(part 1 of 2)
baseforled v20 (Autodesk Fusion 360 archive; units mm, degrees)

design "baseforled" references "Petal", "linkagestopper", "FinalprojectPCBnew", "cup", "Seervo-horn", "sensormountnyt1", "Linkage", "Tower Pro MG90S Micro servo"
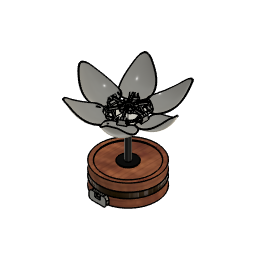
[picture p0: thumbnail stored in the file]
description: STEP AP214
part number: Tower Pro MG90S Micro servo
description: Part Number
part number: Untitled
parameter "d13_1" = 0
parameter "d14_1" = 10
sketch "Sketch1" plane through (0, 0, 0) normal (0, 0, 1) x axis (1, 0, 0)
  circle C1 centre (0, 0) radius 50
  point P1 (0, 0)
  point P2 (0, 0)
  coincident P1 P2
  dimension "d1" diameter C1 = 100
extrude "Extrude1" new body sketch "Sketch1" along normal blind 40
sketch "Sketch2" plane through (0, 0, 40) normal (0, 0, 1) x axis (-1, 0, 0)
  line L1 (15, 0) -> (0, 0)
  circle C1 centre (0, 0) radius 50
  circle C2 centre (0, 0) radius 15
  circle C3 centre (0, 0) radius 5
  circle C4 centre (0, 0) radius 1.5
  circle C5 centre (11, 0) radius 2.5
  circle C6 centre (-5.5, 9.5263) radius 2.5
  circle C7 centre (-5.5, -9.5263) radius 2.5
  point P3 (0, 0)
  point P6 (0, 0)
  point P7 (15, 0)
  point P8 (11, 0)
  point P4 (0, 0)
  concentric C1 C2
  concentric C2 C3
  concentric C3 C4
  coincident P3 P6
  coincident C2 P7
  horizontal L1
  coincident L1 P8
  dimension "d4" diameter C2 = 30
  dimension "d5" diameter C3 = 10
  dimension "d6" diameter C4 = 3
  dimension "d10" diameter C5 = 5
  dimension "d11" distance P4 P8 = 11
  dimension "d13" C-Pattern1-Angle = 360
shell "Shell1" innerThickness 6
extrude "Extrude2" cut sketch "Sketch2" profile of C3 C4 against normal blind 6
extrude "Extrude1" new body sketch "Sketch2" profile of C2 C3 C4 C5 C6 C7 against normal blind 3
extrude "Extrude2" add sketch "Sketch2" profile of C5 C6 C7 against normal blind 6
extrude "Extrude3" add sketch "Sketch2" profile of C3 C4 against normal blind 8 and along normal blind 50
extrude "Extrude3" add of existing geometry blind 2
combine "Combine1"
sketch "Sketch3" plane through (0, 0, 34) normal (0, 0, 1) x axis (-1, 0, 0)
  circle C1 centre (-5.5, 9.5263) radius 2.5
  circle C2 centre (11, 0) radius 2.5
  circle C3 centre (-5.5, -9.5263) radius 2.5
  circle C4 centre (11, 0) radius 1.5
  circle C5 centre (-5.5, -9.5263) radius 1.5
  circle C6 centre (-5.5, 9.5263) radius 1.5
  concentric C2 C4
  concentric C3 C5
  concentric C1 C6
  dimension "d24" diameter C4 = 3
  dimension "d25" diameter C5 = 3
  dimension "d26" diameter C6 = 3
extrude "Extrude4" cut sketch "Sketch3" profile of C4 C5 C6 against normal blind 2
sketch "Sketch4" plane through (0, 0, 0) normal (0, 0, -1) x axis (1, 0, 0)
  line L1 (-47, 0) -> (0, 0)
  circle C1 centre (0, 0) radius 44
  circle C2 centre (0, 0) radius 50
  circle C3 centre (0, 0) radius 47
  circle C4 centre (-37, 0) radius 1.5
  circle C5 centre (0, -37) radius 1.5
  circle C6 centre (37, 0) radius 1.5
  circle C7 centre (0, 37) radius 1.5
  point P3 (0, 0)
  point P4 (0, 0)
  point P6 (-37, 0)
  point P5 (-47, 0)
  concentric C1 C3
  coincident P3 P4
  horizontal L1
  coincident L1 P6
  coincident C3 P5
  dimension "d31" diameter C3 = 94
  dimension "d32" diameter C4 = 3
  dimension "d33" distance P5 P6 = 10
  dimension "d35" C-Pattern1-Angle = 360
extrude "Extrude5" cut sketch "Sketch4" profile of C1 C3 against normal blind 2.8
extrude "Extrude1" new body sketch "Sketch4" profile of C1 C3 C4 C5 C6 C7 against normal blind 2.8
external_derived "ExternalDerived1"
derived_instance "DerivedInstance1"
component_insert "Component Insert3"
component_insert "Component Insert4"
position "Position1"
sketch "Sketch5" plane through (0, 0, 90) normal (0, 0, 1) x axis (-1, 0, 0)
  circle C1 centre (0, 0) radius 1.5
  circle C2 centre (0, 0) radius 5
  circle C3 centre (0, 0) radius 1
  concentric C1 C3
extrude "Extrude1" new body sketch "Sketch5" profile of C3 against normal blind 100
sketch "Sketch6" plane through (0, 0, 0) normal (0, 1, 0) x axis (1, 0, 0)
  circle C1 centre (0, 13) radius 1.25
  circle C2 centre (0, 13) radius 2
  concentric C1 C2
  dimension "d42" diameter C1 = 2.5
sketch "Sketch8" plane through (0, 0, 0) normal (0, 0, 1) x axis (1, 0, 0)
  circle C1 centre (0, -4) radius 1
sketch "Sketch9" plane through (0, 0, 0) normal (1, 0, 0) x axis (0, 1, 0)
  arc A1 centre (-3.1069, -12.5) radius 1.0235 clockwise from (-4, -13) to (-3.0095, -11.4811)
position "Position2"
position "Position3"
extrude "Extrude8" cut of existing geometry blind -6
move "Move3"
position "Position13"
sketch "Sketch14" plane through (0, -3.0543, 0) normal (0, 1, 0) x axis (-1, 0, 0)
  line L1 (3.8332, 6.2534) -> (-10.7858, 4.8708)
  line L2 (-10.763, 11.5994) -> (3.8332, 10.2534)
  line L3 (-1.5977, 13.5422) -> (-4.0509, 13.5422)
  line L4 (-1.5977, 5.7397) -> (-1.5977, 13.5422)
  line L5 (-4.0509, 5.7397) -> (-1.5977, 5.7397)
  line L6 (-4.0509, 13.5422) -> (-4.0509, 5.7397)
  circle C1 centre (-0.3736, 8.2236) radius 0.5
  circle C2 centre (-2.9004, 8.2207) radius 0.5
  circle C3 centre (4.4334, 8.2381) radius 0.5
  circle C4 centre (-5.3079, 8.2364) radius 0.5
  circle C5 centre (2.0164, 8.2396) radius 0.5
  arc A1 centre (-12.177, 8.2398) radius 3.645 clockwise from (-10.763, 11.5994) to (-10.7858, 4.8708)
  arc A2 centre (3.6441, 8.2534) radius 2.0089 clockwise from (3.8332, 10.2534) to (3.8332, 6.2534)
  point P15 (-1.5977, 5.7397)
  horizontal L3
  vertical L4
  horizontal L5
  vertical L6
  coincident L1 P15
extrude "Extrude12" new body sketch "Sketch14" profile of C2 L2 L3 L4 L5 L6 along normal blind 2
extrude "Extrude13" add of existing geometry blind 3
extrude "Extrude14" add of existing geometry blind 1
extrude "Extrude15" add of existing geometry blind 1
position "Position14"
sketch "Sketch15" plane through (0, -1.0543, 0) normal (0, 1, 0) x axis (-1, 0, 0)
  line L1 (-0.5977, 5.7397) -> (-5.0509, 5.7397)
  line L2 (-0.5977, 16.5422) -> (-0.5977, 5.7397)
  line L3 (-5.0509, 16.5422) -> (-0.5977, 16.5422)
  line L4 (-5.0509, 5.7397) -> (-5.0509, 16.5422)
  circle C1 centre (-2.9004, 8.2207) radius 0.5
  circle C2 centre (-3, 13) radius 1
extrude "Extrude16" cut sketch "Sketch15" profile of C2 against normal blind 4
move "Move4"
position "Position15"
sketch "Sketch16" plane through (0, -1.0543, 0) normal (0, 1, 0) x axis (-1, 0, 0)
  line L1 (-0.5977, 5.7397) -> (-5.0509, 5.7397)
  line L2 (-0.5977, 16.5422) -> (-0.5977, 5.7397)
  line L3 (-5.0509, 16.5422) -> (-0.5977, 16.5422)
  line L4 (-5.0509, 5.7397) -> (-5.0509, 16.5422)
  circle C1 centre (-3, 13) radius 1
  circle C2 centre (-2.9004, 8.2207) radius 0.5
  circle C3 centre (-2.9004, 8.2207) radius 0.6945
  concentric C2 C3
extrude "Extrude17" new body sketch "Sketch16" profile of C2 C3 along normal blind 0.4
sketch "Sketch17" plane through (0, -0.6543, 0) normal (0, 1, 0) x axis (-1, 0, 0)
  line L1 (-2.8, 8.7) -> (-3, 8.7)
  line L2 (-2.8, 7.8) -> (-2.8, 8.7)
  line L3 (-3, 7.8) -> (-2.8, 7.8)
  line L4 (-3, 8.7) -> (-3, 7.8)
  line L5 (-2.5, 8.4) -> (-3.3, 8.4)
  line L6 (-2.5, 8.2) -> (-2.5, 8.4)
  line L7 (-3.3, 8.2) -> (-2.5, 8.2)
  line L8 (-3.3, 8.4) -> (-3.3, 8.2)
  circle C1 centre (-2.9004, 8.2207) radius 0.6945
  horizontal L1
  vertical L2
  horizontal L3
  vertical L4
  horizontal L5
  vertical L6
  horizontal L7
  vertical L8
extrude "Extrude18" cut sketch "Sketch17" profile of L1 L2 L3 L4 L5 L6 L7 L8 against normal blind 0.1
fillet "Fillet2" radius 0.15
fillet "Fillet3" radius 0.05
sketch "Sketch18" plane through (0, -1.0543, 0) normal (0, -1, 0) x axis (1, 0, 0)
  circle C1 centre (2.9004, 8.2207) radius 0.6945
  circle C2 centre (2.9004, 8.2207) radius 0.3922
  concentric C1 C2
extrude "Extrude19" add sketch "Sketch18" profile of C2 along normal blind 5
thread "Thread1" ThreadOffset 0 ThreadLength 4.7
sketch "Sketch19" plane through (0, -6.0543, 0) normal (0, -1, 0) x axis (1, 0, 0)
  line L1 (3.2968, 8.2207) -> (3.0986, 7.8774)
  line L2 (3.0986, 8.5639) -> (3.2968, 8.2207)
  line L3 (2.7022, 8.5639) -> (3.0986, 8.5639)
  line L4 (2.5041, 8.2207) -> (2.7022, 8.5639)
  line L5 (2.7022, 7.8774) -> (2.5041, 8.2207)
  line L6 (3.0986, 7.8774) -> (2.7022, 7.8774)
  line L7 (3.4502, 8.2207) -> (3.1753, 7.7446)
  line L8 (3.1753, 8.6968) -> (3.4502, 8.2207)
  line L9 (2.6255, 8.6968) -> (3.1753, 8.6968)
  line L10 (2.3506, 8.2207) -> (2.6255, 8.6968)
  line L11 (2.6255, 7.7446) -> (2.3506, 8.2207)
  line L12 (3.1753, 7.7446) -> (2.6255, 7.7446)
  circle C1 centre (2.9004, 8.2207) radius 0.3432
  point P2 (2.9004, 8.2207)
  point P9 (2.9004, 8.2207)
  point P16 (2.9004, 8.2207)
  coincident P2 P9
  coincident P9 P16
extrude "Extrude20" new body sketch "Sketch19" profile of L1 L2 L3 L4 L5 L6 L7 L8 L9 L10 L11 L12 against normal blind 0.3
move "Move5"
fillet "Fillet4" radius 0.25
sketch "Sketch20" plane through (0, 0, 2.1397) normal (0, 0, -1) x axis (1, 0, 0)
  line L1 (-4.0751, 30.4976) -> (17.8749, 30.4976)
  line L2 (-4.0751, 20.1476) -> (-4.0751, 30.4976)
  line L3 (17.8749, 20.1476) -> (-4.0751, 20.1476)
  line L4 (17.8749, 30.4976) -> (17.8749, 20.1476)
  line L5 (-9.5017, 18) -> (23, 18)
  line L6 (-9.5017, 25.3226) -> (-9.5017, 18)
  line L7 (23, 25.3226) -> (-9.5017, 25.3226)
  line L8 (23, 18) -> (23, 25.3226)
  line L9 (18.8749, 18) -> (23, 18)
  line L10 (18.8749, 25.3226) -> (18.8749, 18)
  line L11 (23, 25.3226) -> (18.8749, 25.3226)
  line L12 (23, 18) -> (23, 25.3226)
  line L13 (-9.5017, 18) -> (-5, 18)
  line L14 (-9.5017, 25.3226) -> (-9.5017, 18)
  line L15 (-5, 25.3226) -> (-9.5017, 25.3226)
  line L16 (-5, 18) -> (-5, 25.3226)
  point P11 (18.8749, 25.3226)
  point P13 (-5, 18)
  horizontal L5
  vertical L6
  horizontal L7
  vertical L8
  horizontal L9
  vertical L10
  horizontal L11
  vertical L12
  coincident L7 P11
  horizontal L13
  vertical L14
  horizontal L15
  vertical L16
  coincident L5 P13
position "Position16"
sketch "Sketch23" plane through (0, -14.8476, 0) normal (0, 1, 0) x axis (-1, 0, 0)
  line L1 (3.7945, 5.0396) -> (3.7945, 16.4396)
  line L2 (8.1195, 5.0396) -> (3.7945, 5.0396)
  line L3 (8.3695, 10.0396) -> (8.3695, 5.2896)
  line L4 (7.5962, 10.0396) -> (8.3695, 10.0396)
  line L5 (8.3695, 11.4396) -> (7.5962, 11.4396)
  line L6 (8.3695, 16.1896) -> (8.3695, 11.4396)
  line L7 (3.7945, 16.4396) -> (8.1195, 16.4396)
  arc A1 centre (8.1195, 5.2896) radius 0.25 clockwise from (8.3695, 5.2896) to (8.1195, 5.0396)
  arc A2 centre (6.2695, 10.7396) radius 1.5 clockwise from (7.5962, 10.0396) to (7.5962, 11.4396)
  arc A3 centre (8.1195, 16.1896) radius 0.25 clockwise from (8.1195, 16.4396) to (8.3695, 16.1896)
  circle C1 centre (6.2695, 10.7396) radius 2
  circle C2 centre (-21.162, 10.6554) radius 2
  concentric A2 C1
  dimension "d172" diameter C1 = 4
  dimension "d173" diameter C2 = 4
move "Move1"
position "Position17"
extrude "Extrude6" cut blind -1
move "Move10"
move "Move12"
move "Move13"
move "Move14"
move "Move15"
move "Move16"
move "Move18"
move_face "MoveFace1"
extrude "Extrude7" add of existing geometry blind 10
sketch "Sketch34" plane through (0, 0, 21.7985) normal (0, 0, -1) x axis (1, 0, 0)
  circle C1 centre (8.9248, 8.0461) radius 1.5
  circle C2 centre (-7.5752, -1.4802) radius 1.5
  circle C3 centre (8.9248, -11.0065) radius 1.5
  circle C4 centre (3.4248, -1.4802) radius 5
  circle C5 centre (3.4248, -1.4802) radius 44
  circle C6 centre (3.4248, -1.4802) radius 14.9303
  concentric C4 C6
  dimension "d484" diameter C1 = 3
extrude "Extrude8" add sketch "Sketch34" profile of C1 C2 C3 C4 C6 against normal blind 15
position "Position18"
extrude "Extrude9" cut of existing geometry blind -5
position "Position19"
extrude "Extrude10" cut of existing geometry blind -5
position "Position20"
sketch "Sketch35" plane through (0, 0, 31.7985) normal (0, 0, -1) x axis (1, 0, 0)
  line L1 (47.1324, -6.5447) -> (-40.2828, -6.5447)
  circle C1 centre (3.4248, -1.4802) radius 44
  circle C2 centre (8.9248, 8.0461) radius 1.5
  circle C3 centre (-7.5752, -1.4802) radius 1.5
  circle C4 centre (8.9248, -11.0065) radius 1.5
  circle C5 centre (3.4248, -1.4802) radius 5
  point P3 (-40.2828, -6.5447)
  point P4 (47.1324, -6.5447)
  coincident C1 P3
  coincident C1 P4
  horizontal L1
extrude "Extrude11" add sketch "Sketch35" profile of C1 L1 along normal blind 20
extrude "Extrude12" cut sketch "Sketch34" profile of C1 C2 C3 C4 C6 against normal blind 15
extrude "Extrude13" new body sketch "Sketch34" profile of C1 C2 C3 C4 C6 against normal blind 15 and against normal blind 10
delete_face "DeleteFace1"
extrude "Extrude14" cut of existing geometry blind 22
extrude "Extrude15" cut of existing geometry blind -20
extrude "Extrude17" add of existing geometry blind 5
sketch "Sketch39" plane through (0, 0, 14.7896) normal (0, 0, -1) x axis (1, 0, 0)
  line L1 (-3.4945, 30.4976) -> (18.4555, 30.4976)
  line L2 (-3.4945, 20.1476) -> (-3.4945, 30.4976)
  line L3 (18.4555, 20.1476) -> (-3.4945, 20.1476)
  line L4 (18.4555, 30.4976) -> (18.4555, 20.1476)
extrude "Extrude38" new body sketch "Sketch20" profile of L2 L3 L4 L5 L6 L7 L8 L9 L10 L11 L12 L13 L14 L15 L16 against normal blind 7 and against normal blind 10
sketch "Sketch40" plane through (0, 0, 9.1397) normal (0, 0, -1) x axis (1, 0, 0)
  line L1 (-9.5017, 18) -> (-9.5017, 25.3226)
  line L2 (23, 18) -> (-9.5017, 18)
  line L3 (23, 25.3226) -> (23, 18)
  line L4 (-9.5017, 25.3226) -> (23, 25.3226)
  line L5 (19.5, 18) -> (23, 18)
  line L6 (19.5, 25.3226) -> (19.5, 18)
  line L7 (23, 25.3226) -> (19.5, 25.3226)
  line L8 (23, 18) -> (23, 25.3226)
  line L9 (-6.0017, 18) -> (-9.5017, 18)
  line L10 (-6.0017, 25.3226) -> (-6.0017, 18)
  line L11 (-9.5017, 25.3226) -> (-6.0017, 25.3226)
  line L12 (-9.5017, 18) -> (-9.5017, 25.3226)
  point P4 (23, 18)
  point P6 (23, 18)
  point P3 (-9.5017, 18)
  point P10 (-9.5017, 18)
  point P7 (19.5, 18)
  point P11 (-6.0017, 18)
  horizontal L5
  vertical L6
  horizontal L7
  vertical L8
  coincident P4 P6
  horizontal L9
  vertical L10
  horizontal L11
  vertical L12
  coincident P3 P10
  dimension "d267" distance P6 P7 = 3.5
  dimension "d268" distance P10 P11 = 3.5
extrude "Extrude39" add sketch "Sketch40" profile of L2 L3 L4 L5 L6 L7 L8 against normal blind 19
extrude "Extrude40" add sketch "Sketch40" profile of L1 L2 L4 L9 L10 L11 L12 against normal blind 19
extrude "Extrude41" add of existing geometry blind 2
extrude "Extrude42" add of existing geometry blind 1
extrude "Extrude44" add of existing geometry blind 1
position "Position22"
sketch "Sketch41" plane through (0, -18, 0) normal (0, 1, 0) x axis (-1, 0, 0)
  line L1 (-18.5, 13.1397) -> (4.0017, 13.1397)
  line L2 (-18.5, 28.1397) -> (-18.5, 13.1397)
  line L3 (-23, 28.1397) -> (-18.5, 28.1397)
  line L4 (-23, 9.1397) -> (-23, 28.1397)
  line L5 (9.5017, 9.1397) -> (-23, 9.1397)
  line L6 (9.5017, 28.1397) -> (9.5017, 9.1397)
  line L7 (4.0017, 28.1397) -> (9.5017, 28.1397)
  line L8 (-6.7491, 31.2966) -> (-6.7491, 5)
  line L9 (4.0017, 13.1397) -> (4.0017, 28.1397)
  circle C1 centre (7.171, 20.7271) radius 1.5
  circle C2 centre (-20.6693, 20.7271) radius 1.5
  perpendicular L5 L8
  symmetric L8 C1 C2
  dimension "d283" diameter C1 = 3
  dimension "d284" diameter C2 = 3
extrude "Extrude45" cut sketch "Sketch41" profile of C1 C2 against normal blind 10
sketch "Sketch42" plane through (0, -14.807, 0) normal (0, 1, 0) x axis (-1, 0, 0)
  line L1 (4.24, 15.1104) -> (4.24, 26.5104)
  line L2 (8.565, 15.1104) -> (4.24, 15.1104)
  line L3 (8.815, 20.1104) -> (8.815, 15.3604)
  line L4 (8.0417, 20.1104) -> (8.815, 20.1104)
  line L5 (8.815, 21.5104) -> (8.0417, 21.5104)
  line L6 (8.815, 26.2604) -> (8.815, 21.5104)
  line L7 (4.24, 26.5104) -> (8.565, 26.5104)
  arc A1 centre (8.565, 15.3604) radius 0.25 clockwise from (8.815, 15.3604) to (8.565, 15.1104)
  arc A2 centre (6.715, 20.8104) radius 1.5 clockwise from (8.0417, 20.1104) to (8.0417, 21.5104)
  arc A3 centre (8.565, 26.2604) radius 0.25 clockwise from (8.565, 26.5104) to (8.815, 26.2604)
  circle C1 centre (6.715, 20.8104) radius 2
  circle C2 centre (-20.7128, 20.8104) radius 2
  concentric A2 C1
  dimension "d287" diameter C1 = 4
  dimension "d288" diameter C2 = 4
extrude "Extrude46" new body sketch "Sketch42" profile of C2 along normal blind 1
extrude "Extrude47" new body sketch "Sketch42" profile of L4 A2 L5 C1 along normal blind 1
sketch "Sketch43" plane through (0, -13.807, 0) normal (0, 1, 0) x axis (-1, 0, 0)
  circle C1 centre (6.715, 20.8104) radius 2
sketch "Sketch44" plane through (0, -13.807, 0) normal (0, 1, 0) x axis (-1, 0, 0)
  line L1 (6.5, 19) -> (6.9, 19)
  line L2 (6.5, 22.6) -> (6.5, 19)
  line L3 (6.9, 22.6) -> (6.5, 22.6)
  line L4 (6.9, 19) -> (6.9, 22.6)
  line L5 (4.9, 20.6) -> (8.6, 20.6)
  line L6 (4.9, 21) -> (4.9, 20.6)
  line L7 (8.6, 21) -> (4.9, 21)
  line L8 (8.6, 20.6) -> (8.6, 21)
  horizontal L1
  vertical L2
  horizontal L3
  vertical L4
  horizontal L5
  vertical L6
  horizontal L7
  vertical L8
extrude "Extrude48" cut sketch "Sketch44" against normal blind 0.2
sketch "Sketch45" plane through (0, -13.807, 0) normal (0, 1, 0) x axis (-1, 0, 0)
  line L1 (-20.9, 19) -> (-20.5, 19)
  line L2 (-20.9, 22.7) -> (-20.9, 19)
  line L3 (-20.5, 22.7) -> (-20.9, 22.7)
  line L4 (-20.5, 19) -> (-20.5, 22.7)
  line L5 (-22.6, 20.6) -> (-18.8, 20.6)
  line L6 (-22.6, 21) -> (-22.6, 20.6)
  line L7 (-18.8, 21) -> (-22.6, 21)
  line L8 (-18.8, 20.6) -> (-18.8, 21)
  circle C1 centre (-20.7128, 20.8104) radius 2
  horizontal L1
  vertical L2
  horizontal L3
  vertical L4
  horizontal L5
  vertical L6
  horizontal L7
  vertical L8
extrude "Extrude49" cut sketch "Sketch45" profile of L1 L2 L3 L4 L5 L6 L7 L8 against normal blind 0.2
move "Move19"
sketch "Sketch46" plane through (0, -25.3226, 0) normal (0, -1, 0) x axis (1, 0, 0)
  line L1 (-9.5017, 28.1397) -> (-4.0017, 28.1397)
  line L2 (-9.5017, 9.1397) -> (-9.5017, 28.1397)
  line L3 (23, 9.1397) -> (-9.5017, 9.1397)
  line L4 (23, 28.1397) -> (23, 9.1397)
  line L5 (18.5, 28.1397) -> (23, 28.1397)
  line L6 (18.5, 13.1397) -> (18.5, 28.1397)
  line L7 (-4.0017, 13.1397) -> (18.5, 13.1397)
  line L8 (-4.0017, 28.1397) -> (-4.0017, 13.1397)
  circle C1 centre (-7.171, 20.7271) radius 1.5
  circle C2 centre (20.6693, 20.7271) radius 1.5
  circle C3 centre (20.6693, 20.7271) radius 0.75
  circle C4 centre (-7.171, 20.7271) radius 0.75
  concentric C2 C3
  concentric C1 C4
  dimension "d297" diameter C3 = 1.5
  dimension "d298" diameter C4 = 1.5
extrude "Extrude50" new body sketch "Sketch46" profile of C3 against normal blind 10
extrude "Extrude51" new body sketch "Sketch46" profile of C4 against normal blind 10
sketch "Sketch47" plane through (0, 0, 28.1397) normal (0, 0, 1) x axis (-1, 0, 0)
  line L1 (-23, 25.3226) -> (-18.5, 25.3226)
  line L2 (-23, 18) -> (-23, 25.3226)
  line L3 (-18.5, 18) -> (-23, 18)
  line L4 (-18.5, 25.3226) -> (-18.5, 18)
  line L5 (-36.5343, 18) -> (-18.5, 18)
  line L6 (-36.5343, 25.2848) -> (-36.5343, 18)
  line L7 (-18.5, 25.2848) -> (-36.5343, 25.2848)
  line L8 (-18.5, 18) -> (-18.5, 25.2848)
  point P5 (-18.5, 18)
  point P6 (-18.5, 18)
  horizontal L5
  vertical L6
  horizontal L7
  vertical L8
  coincident P5 P6
extrude "Extrude52" add sketch "Sketch47" profile of L2 L5 L6 L7 against normal blind 2
sketch "Sketch48" plane through (0, 0, 28.1397) normal (0, 0, 1) x axis (-1, 0, 0)
  line L1 (9.5017, 18) -> (4.0017, 18)
  line L2 (9.5017, 25.3226) -> (9.5017, 18)
  line L3 (4.0017, 25.3226) -> (9.5017, 25.3226)
  line L4 (22.0017, 18) -> (4.0017, 18)
  line L5 (22.0017, 25.3452) -> (22.0017, 18)
  line L6 (4.0017, 25.3452) -> (22.0017, 25.3452)
  line L7 (4.0017, 18) -> (4.0017, 25.3452)
  line L8 (4.0017, 18) -> (4.0017, 25.3226)
  point P3 (4.0017, 18)
  point P6 (4.0017, 18)
  point P7 (22.0017, 18)
  horizontal L4
  vertical L5
  horizontal L6
  vertical L7
  coincident P3 P6
  dimension "d305" distance P6 P7 = 18
extrude "Extrude53" add sketch "Sketch48" profile of L2 L4 L5 L6 against normal blind 2
sketch "Sketch49" plane through (0, 0, 26.1397) normal (0, 0, -1) x axis (1, 0, 0)
  line L1 (-9.5017, 25.3226) -> (-9.5017, 18)
  line L2 (-4.0017, 25.3226) -> (-9.5017, 25.3226)
  line L3 (-22.0017, 18) -> (-22.0017, 25.3452)
  line L4 (-9.5017, 18) -> (-22.0017, 18)
  line L5 (-15.2647, 21.6317) -> (-13.7647, 21.6317)
  line L6 (-19.8258, 21.6317) -> (-18.3258, 21.6317)
  line L7 (-4.0017, 25.3452) -> (-4.0017, 25.3226)
  line L8 (-22.0017, 25.3452) -> (-4.0017, 25.3452)
  circle C1 centre (-12.265, 21.6613) radius 1.5
  circle C2 centre (-16.8261, 21.665) radius 1.5
  circle C3 centre (-21.4168, 21.665) radius 1.5
  point P9 (-13.7647, 21.6317)
  point P11 (-18.3258, 21.6317)
  point P10 (-15.2647, 21.6317)
  point P12 (-19.8258, 21.6317)
  coincident C1 P9
  horizontal L5
  coincident C2 P11
  horizontal L6
  dimension "d308" diameter C1 = 3
  dimension "d309" diameter C2 = 3
  dimension "d310" diameter C3 = 3
  dimension "d311" distance P9 P10 = 1.5
  dimension "d312" distance P11 P12 = 1.5
extrude "Extrude54" add of existing geometry blind 0.5
extrude "Extrude55" cut sketch "Sketch49" profile of C1 C2 C3 against normal blind 6
sketch "Sketch50" plane through (0, 0, 26.1397) normal (0, 0, -1) x axis (1, 0, 0)
  line L1 (36.5343, 25.2848) -> (36.5343, 18)
  line L2 (23, 25.2848) -> (36.5343, 25.2848)
  line L3 (23, 18) -> (23, 25.2848)
  line L4 (36.5343, 18) -> (23, 18)
  line L5 (28.1613, 21.6424) -> (26.6613, 21.6424)
  line L6 (32.6612, 21.6406) -> (31.1612, 21.6406)
  circle C1 centre (25.1633, 21.721) radius 1.5
  circle C2 centre (29.6633, 21.5608) radius 1.5
  circle C3 centre (34.1222, 21.527) radius 1.5
  point P9 (26.6613, 21.6424)
  point P11 (31.1612, 21.6406)
  point P10 (28.1613, 21.6424)
  point P12 (32.6612, 21.6406)
  coincident C1 P9
  perpendicular L3 L5
  coincident C2 P11
  horizontal L6
  dimension "d317" diameter C1 = 3
  dimension "d318" diameter C2 = 3
  dimension "d319" diameter C3 = 3
  dimension "d320" distance P9 P10 = 1.5
  dimension "d321" distance P11 P12 = 1.5
extrude "Extrude56" cut sketch "Sketch50" profile of C1 C2 C3 against normal blind 8
move "Move20"
move "Move21"
fillet "Fillet7" radius 2
move "Move22"
move "Move23"
sketch "Sketch51" plane through (0, 0, 11.7985) normal (0, 0, -1) x axis (1, 0, 0)
  line L1 (-40.2828, -6.5447) -> (-10.6203, -6.5447)
  line L2 (17.4699, -6.5447) -> (47.1324, -6.5447)
  arc A1 centre (3.4248, -1.4802) radius 14.9303 clockwise from (17.4699, -6.5447) to (-10.6203, -6.5447)
  arc A2 centre (3.4248, -1.4802) radius 44 clockwise from (47.1324, -6.5447) to (-40.2828, -6.5447)
  circle C1 centre (29.6606, -23.6235) radius 1.5
  circle C2 centre (-22.9024, -23.8793) radius 1.5
component_from_bodies "Body->Comp2"
component_from_bodies "Body->Comp3"
component_from_bodies "Body->Comp5"
component_from_bodies "Body->Comp6"
component_from_bodies "Body->Comp7"
component_from_bodies "Body->Comp8"
component_from_bodies "Body->Comp9"
component_from_bodies "Body->Comp10"
delete_face "DeleteFace1"
remove_body "RemoveBody12"
remove_instance "RemoveInstance2"
remove_instance "RemoveInstance3"
remove_instance "RemoveInstance4"
remove_instance "RemoveInstance5"
remove_instance "RemoveInstance6"
joint "Assemble9" alignAngle -120 alignOffsetX 0 alignOffsetY 0 alignOffsetZ 0
position "Position29"
joint "Assemble10" alignAngle -90 alignOffsetX 0 alignOffsetY 0 alignOffsetZ 0
position "Position30"
joint "Assemble11" alignAngle 30 alignOffsetX 0 alignOffsetY 0 alignOffsetZ 1
joint "Assemble12" alignAngle 90 alignOffsetX 0 alignOffsetY 0 alignOffsetZ 0
position "Position31"
position "Position32"
position "Position34"
position "Position36"
position "Position37"
as_built_joint "As-built24"
position "Position33"
sketch "Sketch52" plane through (0, 0, 0) normal (0, 1, 0) x axis (1, 0, 0)
  line L1 (81, 5) -> (76, 5)
  line L2 (81, -10) -> (81, 5)
  line L3 (76, -10) -> (81, -10)
  line L4 (76, 5) -> (76, -10)
  line L5 (78.5, -10) -> (78.5, 5)
  line L6 (76, -2.5) -> (81, -2.5)
  circle C1 centre (78.5, -7) radius 1
  circle C2 centre (78.5, 2) radius 1
  point P6 (78.5, 5)
  point P7 (78.5, -10)
  point P8 (81, -2.5)
  point P9 (76, -2.5)
  point P10 (78.5, -7)
  point P11 (78.5, 2)
  point P2 (76, 5)
  point P5 (76, -10)
  horizontal L1
  vertical L2
  horizontal L3
  vertical L4
  midpoint L1 P6
  midpoint L3 P7
  midpoint L2 P8
  midpoint L4 P9
  coincident L5 P10
  coincident L5 P11
  dimension "d370" distance L2 L4 = 5
  dimension "d371" distance P2 P5 = 15
  dimension "d372" diameter C1 = 2
  dimension "d373" diameter C2 = 2
  dimension "d374" distance L1 P11 = 3
  dimension "d375" distance L3 P10 = 3 (= "d374")
extrude "Extrude1" new body sketch "Sketch52" profile of L1 L2 L3 L4 C1 C2 along normal blind 2
fillet "Fillet1" radius 2.5
joint "Assemble13" alignAngle -180 alignOffsetX 0 alignOffsetY 0 alignOffsetZ -0.8
position "Position35"
position "Position38"
position "Position39"
position "Position40"
as_built_joint "As-built25" OffsetX 0 OffsetY 0 OffsetZ 0 AngleZ 0
position "Position41"
extrude "Extrude19" add of existing geometry blind 10
remove_instance "RemoveInstance7"
position "Position42"
position "Position43"
component_insert "Component Insert11"
position "Position46" sketch "Sketch2"
as_built_joint "As-built28" sketch "Sketch2"
position "Position47" sketch "Sketch2"
extrude "Extrude21" add of existing geometry blind 0.7
sketch "Sketch57" plane through (0, 0, 9.4519) normal (0, 0, -1) x axis (1, 0, 0)
  line L1 (33.5509, -9.3114) -> (33.5509, -33.3114)
  line L2 (-26.4491, -9.3114) -> (33.5509, -9.3114)
  line L3 (-26.4784, -33.2794) -> (-26.4491, -9.3114)
  arc A1 centre (3.5537, -0.5824) radius 44.3961 clockwise from (33.5509, -33.3114) to (-26.4784, -33.2794)
  circle C1 centre (30.0509, -14.8114) radius 1.5
  circle C2 centre (10.8998, -27.2344) radius 0.4
  circle C3 centre (-19.9491, -14.8114) radius 1.5
  circle C4 centre (-4.3352, -27.2344) radius 0.4
  circle C5 centre (10.8998, -29.7744) radius 0.4
  circle C6 centre (10.8998, -32.3144) radius 0.4
  circle C7 centre (10.8998, -34.8544) radius 0.4
  circle C8 centre (10.8998, -37.3944) radius 0.4
  circle C9 centre (10.8998, -39.9344) radius 0.4
  circle C10 centre (10.8998, -42.4744) radius 0.4
  circle C11 centre (-4.3352, -29.7744) radius 0.4
  circle C12 centre (-4.3352, -32.3144) radius 0.4
  circle C13 centre (-4.3352, -34.8544) radius 0.4
  circle C14 centre (-4.3352, -37.3944) radius 0.4
  circle C15 centre (-4.3352, -39.9344) radius 0.4
  circle C16 centre (-4.3352, -42.4744) radius 0.4
extrude "Extrude22" cut sketch "Sketch57" profile of C3 against normal blind 5
position "Position48"
extrude "Extrude23" cut sketch "Sketch57" profile of C1 against normal blind 5
sketch "Sketch58" plane through (0, 0, -0.2015) normal (0, 0, -1) x axis (1, 0, 0)
  line L1 (7.6317, -47.0732) -> (6.3817, -47.0732)
  line L2 (7.6317, -39.7732) -> (7.6317, -47.0732)
  line L3 (6.3817, -39.7732) -> (7.6317, -39.7732)
  line L4 (6.3817, -47.0732) -> (6.3817, -39.7732)
  line L5 (-0.0583, -47.0732) -> (-1.3083, -47.0732)
  line L6 (-0.0583, -39.7732) -> (-0.0583, -47.0732)
  line L7 (-1.3083, -39.7732) -> (-0.0583, -39.7732)
  line L8 (-1.3083, -47.0732) -> (-1.3083, -39.7732)
  line L9 (-0.0583, -39.7732) -> (6.3817, -39.7732)
  line L10 (-0.0583, -47.0732) -> (-0.0583, -39.7732)
  line L11 (6.3817, -47.0732) -> (-0.0583, -47.0732)
  line L12 (6.3817, -39.7732) -> (6.3817, -47.0732)
  line L13 (2.2112, -41.6732) -> (1.0112, -41.6732)
  line L14 (2.2112, -42.3732) -> (2.2112, -41.6732)
  line L15 (1.0112, -42.3732) -> (2.2112, -42.3732)
  line L16 (1.0112, -41.6732) -> (1.0112, -42.3732)
  line L17 (5.3121, -41.6732) -> (4.1121, -41.6732)
  line L18 (5.3121, -42.3732) -> (5.3121, -41.6732)
  line L19 (4.1121, -42.3732) -> (5.3121, -42.3732)
  line L20 (4.1121, -41.6732) -> (4.1121, -42.3732)
  line L21 (-5.7357, -33.2272) -> (-4.4022, -33.2272)
  line L22 (-5.7357, -34.2432) -> (-5.7357, -33.2272)
  line L23 (-4.4022, -34.2432) -> (-5.7357, -34.2432)
  line L24 (-5.7357, -35.7672) -> (-4.4022, -35.7672)
  line L25 (-5.7357, -36.7832) -> (-5.7357, -35.7672)
  line L26 (-4.4022, -36.7832) -> (-5.7357, -36.7832)
  line L27 (-5.7357, -38.3072) -> (-4.4022, -38.3072)
  line L28 (-5.7357, -39.3232) -> (-5.7357, -38.3072)
  line L29 (-4.4022, -39.3232) -> (-5.7357, -39.3232)
  line L30 (-5.7357, -40.8472) -> (-4.4022, -40.8472)
  line L31 (-5.7357, -41.8632) -> (-5.7357, -40.8472)
  line L32 (-4.4022, -41.8632) -> (-5.7357, -41.8632)
  line L33 (-5.7357, -43.3872) -> (-4.4022, -43.3872)
  line L34 (-5.7357, -43.6412) -> (-5.7357, -43.3872)
  line L35 (10.1393, -45.5462) -> (-3.8307, -45.5462)
  line L36 (12.0443, -43.3872) -> (12.0443, -43.6412)
  line L37 (10.7108, -43.3872) -> (12.0443, -43.3872)
  line L38 (12.0443, -41.8632) -> (10.7108, -41.8632)
  line L39 (12.0443, -40.8472) -> (12.0443, -41.8632)
  line L40 (10.7108, -40.8472) -> (12.0443, -40.8472)
  line L41 (12.0443, -39.3232) -> (10.7108, -39.3232)
  line L42 (12.0443, -38.3072) -> (12.0443, -39.3232)
  line L43 (10.7108, -38.3072) -> (12.0443, -38.3072)
  line L44 (12.0443, -36.7832) -> (10.7108, -36.7832)
  line L45 (12.0443, -35.7672) -> (12.0443, -36.7832)
  line L46 (10.7108, -35.7672) -> (12.0443, -35.7672)
  line L47 (12.0443, -34.2432) -> (10.7108, -34.2432)
  line L48 (12.0443, -33.2272) -> (12.0443, -34.2432)
  line L49 (10.7108, -33.2272) -> (12.0443, -33.2272)
  line L50 (12.0443, -31.7032) -> (10.7108, -31.7032)
  line L51 (12.0443, -30.6872) -> (12.0443, -31.7032)
  line L52 (10.7108, -30.6872) -> (12.0443, -30.6872)
  line L53 (12.0443, -29.1632) -> (10.7108, -29.1632)
  line L54 (12.0443, -28.1472) -> (12.0443, -29.1632)
  line L55 (10.7108, -28.1472) -> (12.0443, -28.1472)
  line L56 (12.0443, -26.6232) -> (10.7108, -26.6232)
  line L57 (12.0443, -26.4962) -> (12.0443, -26.6232)
  line L58 (-3.8307, -24.5912) -> (10.1393, -24.5912)
  line L59 (-5.7357, -26.6232) -> (-5.7357, -26.4962)
  line L60 (-4.4022, -26.6232) -> (-5.7357, -26.6232)
  line L61 (-5.7357, -28.1472) -> (-4.4022, -28.1472)
  line L62 (-5.7357, -29.1632) -> (-5.7357, -28.1472)
  line L63 (-4.4022, -29.1632) -> (-5.7357, -29.1632)
  line L64 (-5.7357, -30.6872) -> (-4.4022, -30.6872)
  line L65 (-5.7357, -31.7032) -> (-5.7357, -30.6872)
  line L66 (-4.4022, -31.7032) -> (-5.7357, -31.7032)
  line L67 (-3.3227, -29.2902) -> (-3.3227, -30.0522)
  line L68 (-2.8147, -30.0522) -> (-2.8147, -29.2902)
  line L69 (7.6946, -44.9112) -> (7.6946, -44.0222)
  line L70 (7.2501, -44.0222) -> (7.2501, -44.9112)
  line L71 (-0.9414, -40.7202) -> (-0.9414, -39.8312)
  line L72 (-1.3859, -39.8312) -> (-1.3859, -40.7202)
  line L73 (7.6946, -40.7202) -> (7.6946, -39.8312)
  line L74 (7.2501, -39.8312) -> (7.2501, -40.7202)
  line L75 (-0.9414, -44.9112) -> (-0.9414, -44.0222)
  line L76 (-1.3859, -44.0222) -> (-1.3859, -44.9112)
  line L77 (7.198, -29.9075) -> (8.0007, -29.9075)
  line L78 (7.198, -28.7035) -> (7.198, -29.9075)
  line L79 (8.0007, -28.7035) -> (7.198, -28.7035)
  line L80 (8.0007, -29.9075) -> (8.0007, -28.7035)
  line L81 (9.1233, -29.2902) -> (9.1233, -30.0522)
  line L82 (9.6313, -30.0522) -> (9.6313, -29.2902)
  line L83 (8.9506, -33.1485) -> (8.148, -33.1485)
  line L84 (8.9506, -34.3525) -> (8.9506, -33.1485)
  line L85 (8.148, -34.3525) -> (8.9506, -34.3525)
  line L86 (8.148, -33.1485) -> (8.148, -34.3525)
  line L87 (8.9506, -30.7025) -> (8.148, -30.7025)
  line L88 (8.9506, -31.9064) -> (8.9506, -30.7025)
  line L89 (8.148, -31.9064) -> (8.9506, -31.9064)
  line L90 (8.148, -30.7025) -> (8.148, -31.9064)
  line L91 (8.9506, -28.7035) -> (8.148, -28.7035)
  line L92 (8.9506, -29.9075) -> (8.9506, -28.7035)
  line L93 (8.148, -29.9075) -> (8.9506, -29.9075)
  line L94 (8.148, -28.7035) -> (8.148, -29.9075)
  line L95 (7.0507, -33.1485) -> (6.2481, -33.1485)
  line L96 (7.0507, -34.3525) -> (7.0507, -33.1485)
  line L97 (6.2481, -34.3525) -> (7.0507, -34.3525)
  line L98 (6.2481, -33.1485) -> (6.2481, -34.3525)
  line L99 (7.0507, -30.7025) -> (6.2481, -30.7025)
  line L100 (7.0507, -31.9064) -> (7.0507, -30.7025)
  line L101 (6.2481, -31.9064) -> (7.0507, -31.9064)
  line L102 (6.2481, -30.7025) -> (6.2481, -31.9064)
  line L103 (7.0507, -28.7035) -> (6.2481, -28.7035)
  line L104 (7.0507, -29.9075) -> (7.0507, -28.7035)
  line L105 (6.2481, -29.9075) -> (7.0507, -29.9075)
  line L106 (6.2481, -28.7035) -> (6.2481, -29.9075)
  line L107 (7.6317, -54) -> (7.6317, -42.1282)
  line L108 (-1.3083, -54) -> (7.6317, -54)
  line L109 (-1.3083, -42.3743) -> (-1.3083, -54)
  line L110 (12.0443, -56) -> (12.0443, -43.3872)
  line L111 (-5.7357, -56) -> (12.0443, -56)
  line L112 (-5.7357, -43.6412) -> (-5.7357, -56)
  circle C1 centre (3.4248, -1.4802) radius 47
  circle C2 centre (3.4248, -1.4802) radius 50
  arc A1 centre (-4.4686, -32.4652) radius 0.7649 clockwise from (-4.4022, -31.7032) to (-4.4022, -33.2272)
  arc A2 centre (-4.4686, -35.0052) radius 0.7649 clockwise from (-4.4022, -34.2432) to (-4.4022, -35.7672)
  arc A3 centre (-4.4686, -37.5452) radius 0.7649 clockwise from (-4.4022, -36.7832) to (-4.4022, -38.3072)
  arc A4 centre (-4.4686, -40.0852) radius 0.7649 clockwise from (-4.4022, -39.3232) to (-4.4022, -40.8472)
  arc A5 centre (-4.4686, -42.6252) radius 0.7649 clockwise from (-4.4022, -41.8632) to (-4.4022, -43.3872)
  arc A6 centre (-3.8306, -43.6412) radius 1.905 clockwise from (-3.8307, -45.5462) to (-5.7357, -43.6412)
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  point P179 (7.6317, -42.1282)
  point P182 (-1.3083, -42.3743)
  point P53 (12.0443, -43.3872)
  point P183 (12.0443, -43.3872)
  point P47 (-5.7357, -43.6412)
  point P186 (-5.7357, -43.6412)
  coincident L2 P179
  perpendicular L107 L108
  coincident L8 P182
  parallel L8 L109
  coincident P53 P183
  perpendicular L37 L110
  perpendicular L110 L111
  coincident P47 P186
  parallel L109 L112
  parallel L107 L110
extrude "Extrude24" cut sketch "Sketch58" against normal blind 10
joint "Assemble14" alignAngle 30 alignOffsetX 0 alignOffsetY 0 alignOffsetZ 0
work_plane "WorkPlane1"
split "Split1"
extrude "Extrude25" cut of existing geometry blind -1
extrude "Extrude26" cut of existing geometry blind -1
move "Move2"
sketch "Sketch59" plane through (0, 0, 20.7985) normal (0, 0, 1) x axis (-1, 0, 0)
  circle C1 centre (-3.4248, -1.4802) radius 14.9303
  circle C2 centre (-3.4248, -1.4802) radius 50
  circle C3 centre (-3.4248, -1.4802) radius 51
  dimension "d413" = 1
extrude "Extrude57" new body sketch "Sketch59" profile of C2 C3 along normal blind 4.73 and against normal blind 4.73
offset_faces "OffsetFaces1" distance 3
split "Split2"
remove_body "RemoveBody4"
remove_body "RemoveBody5"
component_insert "Component Insert12"
derived_base_feature "Derived Base Feature1" bodies "Body1 (Context1)"
base_feature "Base Feature1"
remove_body "RemoveBody1"
extrude "Extrude10" add of existing geometry blind 3 named "d37_1"
extrude "Extrude11" add of existing geometry blind 3 named "d39_1"
extrude "Extrude12" add of existing geometry blind 3 named "d41_1"
move "Move8"
combine "Combine3"
combine "Combine4"
combine "Combine5"
remove_instance "RemoveInstance9"
as_built_joint "As-built29"
thread "Thread1" ThreadOffset 0 ThreadLength 7
sketch "Sketch61" plane through (0, 0, 89.597) normal (0, 0, 1) x axis (-1, 0, 0)
  curve K1 (-0.0797, -3.4063) -> (-5.8098, -5.6112)
  curve K2 (-5.8098, -5.6112) -> (-6.7654, 0.4537)
  arc A1 centre (-3.4248, -1.4802) radius 3.86 clockwise from (-6.7654, 0.4537) to (-0.0797, -3.4063)
  circle C1 centre (-3.4248, -1.4802) radius 1.5
sketch "Sketch62" plane through (0, 0, 31.597) normal (0, 0, -1) x axis (1, 0, 0)
  arc A1 centre (3.6523, -1.3129) radius 5 clockwise from (6.4993, -5.4232) to (0.5778, 2.6301)
  arc A2 centre (3.4248, -1.4802) radius 5 clockwise from (0.5778, 2.6301) to (6.4993, -5.4232)
  circle C1 centre (3.4248, -1.4802) radius 1.5
combine "Combine3"
combine "Combine6"
remove_instance "RemoveInstance10"
component_insert "Component Insert14"
position "Position50"
position "Position51"
sketch "Sketch63" plane through (0, 0, 25.5285) normal (0, 0, -1) x axis (1, 0, 0)
  circle C1 centre (3.4248, -1.4802) radius 47
  circle C2 centre (3.4248, -1.4802) radius 50
  circle C3 centre (3.4248, -1.4802) radius 45
  concentric C1 C3
  dimension "d434" distance C2 C3 = 5
extrude "Extrude30" cut sketch "Sketch63" to an object
sketch "Sketch64" plane through (0, 0, 4.5985) normal (0, 0, -1) x axis (1, 0, 0)
  line L1 (-1.3083, -45.5462) -> (-1.3083, -48.2413)
  line L2 (-3.8307, -45.5462) -> (-1.3083, -45.5462)
  line L3 (7.6317, -45.5462) -> (10.1393, -45.5462)
  line L4 (7.6317, -48.2916) -> (7.6317, -45.5462)
  line L5 (-40.2828, -6.5447) -> (-10.6203, -6.5447)
  line L6 (17.4699, -6.5447) -> (47.1324, -6.5447)
  line L7 (14.2593, 9.495) -> (10.9962, 9.495)
  line L8 (21.6093, 9.495) -> (17.6593, 9.495)
  line L9 (24.8843, 33.545) -> (24.8843, 33.045)
  line L10 (24.8843, 33.045) -> (24.8843, 32.545)
  line L11 (26.1843, 19.395) -> (26.6843, 19.395)
  line L12 (26.1843, 19.395) -> (21.8593, 19.395)
  line L13 (7.1093, 15.245) -> (-0.4407, 15.245)
  line L14 (21.8593, 22.195) -> (21.8593, 19.395)
  line L15 (-0.6907, 19.395) -> (-0.6907, 22.195)
  line L16 (13.5221, 5.8337) -> (13.5221, 8.7063)
  curve K1 (13.5221, 8.7063) -> (14.0093, 8.995)
  line L17 (14.0093, 8.995) -> (14.1047, 8.995)
  line L18 (14.1047, 8.995) -> (14.2593, 8.995)
  line L19 (17.6593, 8.995) -> (17.8139, 8.995)
  line L20 (17.1055, 5.545) -> (16.5619, 5.545)
  line L21 (17.5369, 5.545) -> (17.1055, 5.545)
  line L22 (16.5619, 5.545) -> (15.9593, 5.545)
  line L23 (15.9593, 5.545) -> (15.3567, 5.545)
  line L24 (14.1047, 5.545) -> (14.0093, 5.545)
  curve K2 (14.0093, 5.545) -> (13.5221, 5.8337)
  line L25 (14.3817, 5.545) -> (14.1047, 5.545)
  line L26 (14.8131, 5.545) -> (14.3817, 5.545)
  line L27 (15.3567, 5.545) -> (14.8131, 5.545)
  line L28 (17.8139, 5.545) -> (17.5369, 5.545)
  line L29 (-0.6407, 22.195) -> (-0.6407, 32.545)
  line L30 (21.8093, 32.545) -> (21.8093, 22.195)
  line L31 (-0.6907, 15.495) -> (-0.6907, 16.895)
  line L32 (21.8593, 15.495) -> (21.8593, 15.245)
  line L33 (21.8593, 16.895) -> (21.8593, 15.495)
  line L34 (26.6843, 19.395) -> (26.6843, 17.145)
  line L35 (-5.5157, 17.145) -> (-5.5157, 19.395)
  line L36 (26.1843, 16.895) -> (21.8593, 16.895)
  line L37 (26.4343, 16.895) -> (26.1843, 16.895)
  line L38 (-0.6907, 19.395) -> (-5.0157, 19.395)
  line L39 (-5.5157, 19.395) -> (-5.0157, 19.395)
  line L40 (-5.0157, 16.895) -> (-5.2657, 16.895)
  line L41 (-0.6907, 16.895) -> (-5.0157, 16.895)
  line L42 (10.0593, 9.495) -> (7.3593, 9.495)
  line L43 (10.9962, 9.495) -> (10.0593, 9.495)
  line L44 (-0.6907, 22.195) -> (-0.6407, 22.195)
  line L45 (21.8093, 22.195) -> (21.8593, 22.195)
  line L46 (-0.7157, 32.545) -> (-0.7157, 37.545)
  line L47 (21.8843, 37.545) -> (21.8843, 33.545)
  line L48 (-0.6407, 32.545) -> (-0.7157, 32.545)
  line L49 (21.8843, 32.545) -> (21.8093, 32.545)
  line L50 (-0.4657, 37.795) -> (21.6343, 37.795)
  line L51 (17.8139, 8.995) -> (17.9093, 8.995)
  line L52 (17.9093, 5.545) -> (17.8139, 5.545)
  line L53 (18.3965, 5.8337) -> (18.3965, 8.7063)
  curve K3 (17.9093, 8.995) -> (18.3965, 8.7063)
  curve K4 (18.3965, 5.8337) -> (17.9093, 5.545)
  line L54 (21.8843, 33.545) -> (24.8843, 33.545)
  line L55 (21.8843, 32.545) -> (24.8843, 32.545)
  line L56 (17.6593, 9.495) -> (17.6593, 8.995)
  line L57 (14.2593, 9.495) -> (14.2593, 8.995)
  line L58 (21.8593, 15.245) -> (21.8593, 9.745)
  line L59 (7.1093, 15.245) -> (7.1093, 9.745)
  line L60 (33.5974, 30.545) -> (22.3093, 30.545)
  line L61 (22.3093, 19.395) -> (22.3093, 30.545)
  line L62 (30.6843, 19.395) -> (22.3093, 19.395)
  line L63 (30.6843, -6.5447) -> (30.6843, 19.395)
  line L64 (-1.1407, 19.395) -> (-1.1407, 42.2823)
  line L65 (-9.5157, 19.395) -> (-1.1407, 19.395)
  line L66 (-9.5157, -6.5447) -> (-9.5157, 19.395)
  line L67 (33.5509, -33.3114) -> (33.5509, -9.3114)
  line L68 (-26.4491, -9.3114) -> (-26.4784, -33.2794)
  line L69 (33.5509, -9.3114) -> (-26.4491, -9.3114)
  arc A1 centre (-3.8306, -43.6412) radius 1.905 clockwise from (-3.8307, -45.5462) to (-5.4959, -44.5664)
  arc A2 centre (3.4248, -1.4802) radius 44 clockwise from (-5.4959, -44.5664) to (11.7301, -44.6893)
  arc A3 centre (10.1393, -43.6412) radius 1.905 clockwise from (11.7301, -44.6893) to (10.1393, -45.5462)
  arc A4 centre (3.4248, -1.4802) radius 47 clockwise from (-1.3083, -48.2413) to (7.6317, -48.2916)
  circle C1 centre (30.0509, -14.8114) radius 1.5
  circle C2 centre (-19.9491, -14.8114) radius 1.5
  arc A5 centre (3.4248, -1.4802) radius 14.9303 clockwise from (17.4699, -6.5447) to (-10.6203, -6.5447)
  arc A6 centre (3.4248, -1.4802) radius 44 clockwise from (47.1324, -6.5447) to (-40.2828, -6.5447)
  arc A7 centre (-0.4657, 37.545) radius 0.25 clockwise from (-0.7157, 37.545) to (-0.4657, 37.795)
  arc A8 centre (21.6343, 37.545) radius 0.25 clockwise from (21.6343, 37.795) to (21.8843, 37.545)
  arc A9 centre (-0.4407, 15.495) radius 0.25 clockwise from (-0.4407, 15.245) to (-0.6907, 15.495)
  arc A10 centre (26.4343, 17.145) radius 0.25 clockwise from (26.6843, 17.145) to (26.4343, 16.895)
  arc A11 centre (-5.2657, 17.145) radius 0.25 clockwise from (-5.2657, 16.895) to (-5.5157, 17.145)
  arc A12 centre (21.6093, 9.745) radius 0.25 clockwise from (21.8593, 9.745) to (21.6093, 9.495)
  arc A13 centre (7.3593, 9.745) radius 0.25 clockwise from (7.3593, 9.495) to (7.1093, 9.745)
  circle C3 centre (3.4248, -1.4802) radius 50
  circle C4 centre (3.4248, -1.4802) radius 14.9303
  arc A14 centre (3.5537, -0.5824) radius 44.3961 clockwise from (33.5509, -33.3114) to (-26.4784, -33.2794)
  circle C5 centre (30.0509, -14.8114) radius 1.5
  circle C6 centre (10.8998, -27.2344) radius 0.4
  circle C7 centre (-19.9491, -14.8114) radius 1.5
  circle C8 centre (-4.3352, -27.2344) radius 0.4
  circle C9 centre (10.8998, -29.7744) radius 0.4
  circle C10 centre (10.8998, -32.3144) radius 0.4
  circle C11 centre (10.8998, -34.8544) radius 0.4
  circle C12 centre (10.8998, -37.3944) radius 0.4
  circle C13 centre (10.8998, -39.9344) radius 0.4
  circle C14 centre (10.8998, -42.4744) radius 0.4
  circle C15 centre (-4.3352, -29.7744) radius 0.4
  circle C16 centre (-4.3352, -32.3144) radius 0.4
  circle C17 centre (-4.3352, -34.8544) radius 0.4
  circle C18 centre (-4.3352, -37.3944) radius 0.4
  circle C19 centre (-4.3352, -39.9344) radius 0.4
  circle C20 centre (-4.3352, -42.4744) radius 0.4
  point P92 (33.5974, 30.545)
  point P95 (30.6843, -6.5447)
  point P96 (-1.1407, 42.2823)
  point P99 (-9.5157, -6.5447)
  coincident A2 P92
  perpendicular L30 L60
  perpendicular L60 L61
  perpendicular L61 L62
  coincident L6 P95
  perpendicular L6 L63
  collinear L12 L62
  coincident A2 P96
  vertical L64
  perpendicular L64 L65
  coincident L5 P99
  perpendicular L5 L66
  collinear L38 L65
  dimension "d439" distance L29 L64 = 0.5
  dimension "d440" distance L35 L66 = 4
  dimension "d441" distance L34 L63 = 4
  dimension "d442" distance L30 L61 = 0.5
  dimension "d443" distance L55 L60 = 2
extrude "Extrude31" add sketch "Sketch64" profile of A2 L5 L6 L60 L61 L62 L63 L64 L65 L66 C4 against normal blind 14.2
sketch "Sketch65" plane through (0, 0, 39.7985) normal (0, 0, 1) x axis (-1, 0, 0)
  circle C1 centre (-3.4248, -1.4802) radius 15
  circle C2 centre (-3.4248, -1.4802) radius 50
  circle C3 centre (-3.4248, -1.4802) radius 43
  concentric C2 C3
  dimension "d446" distance C2 C3 = 7
extrude "Extrude32" cut sketch "Sketch65" profile of C1 C3 against normal blind 1.5
sketch "Sketch66" plane through (0, 0, 20.7985) normal (0, 0, 1) x axis (-1, 0, 0)
  line L1 (40.2828, -6.5447) -> (10.6203, -6.5447)
  line L2 (-30.6843, -6.5447) -> (-47.1324, -6.5447)
  line L3 (-17.4699, -6.5447) -> (-30.6843, -6.5447)
  line L4 (30.2828, -6.5447) -> (43.2828, -6.5447)
  line L5 (30.2828, -14.5447) -> (30.2828, -6.5447)
  line L6 (43.2828, -14.5447) -> (30.2828, -14.5447)
  line L7 (43.2828, -6.5447) -> (43.2828, -14.5447)
  circle C1 centre (-3.4248, -1.4802) radius 45
  circle C2 centre (-3.4248, -1.4802) radius 14.9303
  circle C3 centre (-30.0509, -14.8114) radius 1.5
  circle C4 centre (19.9491, -14.8114) radius 1.5
  arc A1 centre (-3.4248, -1.4802) radius 14.9303 clockwise from (10.6203, -6.5447) to (-17.4699, -6.5447)
  arc A2 centre (-3.4248, -1.4802) radius 44 clockwise from (40.2828, -6.5447) to (-47.1324, -6.5447)
  point P8 (40.2828, -6.5447)
  horizontal L4
  vertical L5
  horizontal L6
  vertical L7
  collinear L1 L4
  dimension "d449" distance P8 L7 = 3
  dimension "d450" distance L4 L6 = 8
  dimension "d451" distance P8 L5 = 10
extrude "Extrude33" cut sketch "Sketch66" profile of C1 L1 A2 L4 L5 L6 L7 against normal blind 4.73
extrude "Extrude34" cut sketch "Sketch66" profile of L1 A2 L4 L5 L6 against normal blind 7.7
fillet "Fillet2" radius 3
fillet "Fillet3" radius 3 3
sketch "Sketch67" plane through (0, 0, 1.7985) normal (0, 0, -1) x axis (1, 0, 0)
  line L1 (-1.3083, -48.2413) -> (-1.3083, -51.2557)
  line L2 (7.6317, -51.3029) -> (7.6317, -48.2916)
  line L3 (7.6317, -51.3029) -> (-1.3083, -51.2557)
  line L4 (3.689, 48.5191) -> (3.1617, -51.2793)
  line L5 (15.6758, 45.9944) -> (15.6494, 40.9944)
  line L6 (-8.3238, 46.1212) -> (15.6758, 45.9944)
  line L7 (-8.3503, 41.1212) -> (-8.3238, 46.1212)
  line L8 (15.6494, 40.9944) -> (-8.3503, 41.1212)
  line L9 (-8.3186, 47.1212) -> (-8.3238, 46.1212)
  line L10 (15.6811, 46.9943) -> (15.6758, 45.9944)
  line L11 (-1.3083, -45.5462) -> (-1.3083, -48.2413)
  line L12 (-3.8307, -45.5462) -> (-1.3083, -45.5462)
  line L13 (-10.6203, -6.5447) -> (-36.7742, -6.5447)
  line L14 (-9.5157, 16.395) -> (-9.5157, 5.9667)
  line L15 (-1.1407, 19.395) -> (-6.5157, 19.395)
  line L16 (-1.1407, 39.4899) -> (-1.1407, 19.395)
  line L17 (22.3093, 30.545) -> (24.7376, 30.545)
  line L18 (22.3093, 19.395) -> (22.3093, 30.545)
  line L19 (27.6843, 19.395) -> (22.3093, 19.395)
  line L20 (30.6843, -6.5447) -> (30.6843, 16.395)
  line L21 (43.6238, -6.5447) -> (30.6843, -6.5447)
  line L22 (7.6317, -45.5462) -> (10.1393, -45.5462)
  line L23 (7.6317, -48.2916) -> (7.6317, -45.5462)
  line L24 (15.6483, 40.7878) -> (15.6494, 40.9944)
  arc A1 centre (3.4248, -1.4802) radius 47 clockwise from (-1.3083, -48.2413) to (7.6317, -48.2916)
  arc A2 centre (3.4248, -1.4802) radius 50 clockwise from (-1.3083, -51.2557) to (7.6317, -51.3029)
  arc A3 centre (-3.8306, -43.6412) radius 1.905 clockwise from (-3.8307, -45.5462) to (-5.4959, -44.5664)
  arc A4 centre (3.4248, -1.4802) radius 44 clockwise from (-5.4959, -44.5664) to (-39.7156, -10.1348)
  arc A5 centre (-36.7742, -9.5447) radius 3 clockwise from (-39.7156, -10.1348) to (-36.7742, -6.5447)
  arc A6 centre (3.4248, -1.4802) radius 14.9303 clockwise from (-10.6203, -6.5447) to (-9.5157, 5.9667)
  arc A7 centre (-6.5157, 16.395) radius 3 clockwise from (-9.5157, 16.395) to (-6.5157, 19.395)
  arc A8 centre (1.8593, 39.4899) radius 3 clockwise from (-1.1407, 39.4899) to (1.7448, 42.4877)
  arc A9 centre (3.4248, -1.4802) radius 44 clockwise from (1.7448, 42.4877) to (26.297, 36.1078)
  arc A10 centre (24.7376, 33.545) radius 3 clockwise from (26.297, 36.1078) to (24.7376, 30.545)
  arc A11 centre (27.6843, 16.395) radius 3 clockwise from (27.6843, 19.395) to (30.6843, 16.395)
  arc A12 centre (43.6238, -9.5447) radius 3 clockwise from (43.6238, -6.5447) to (46.5652, -10.1348)
  arc A13 centre (3.4248, -1.4802) radius 44 clockwise from (46.5652, -10.1348) to (11.7301, -44.6893)
  arc A14 centre (10.1393, -43.6412) radius 1.905 clockwise from (11.7301, -44.6893) to (10.1393, -45.5462)
  arc A15 centre (3.4248, -1.4802) radius 47 clockwise from (-1.3083, -48.2413) to (7.6317, -48.2916)
  arc A16 centre (-6.1467, 43.3016) radius 3.1 clockwise from (-3.9663, 41.098) to (-8.3271, 45.5052)
  point P2 (-1.3083, -51.2557)
  point P7 (-1.3083, -51.2557)
  point P6 (7.6317, -51.3029)
  point P8 (7.6317, -51.3029)
  point P9 (3.1617, -51.2793)
  point P10 (3.689, 48.5191)
  point P15 (-8.3186, 47.1212)
  point P16 (15.6811, 46.9943)
  point P52 (15.6483, 40.7878)
  point P54 (-8.3271, 45.5052)
  point P53 (-3.9663, 41.098)
  point P14 (-8.3503, 41.1212)
  point P13 (-8.3238, 46.1212)
  coincident P2 P7
  coincident P6 P8
  midpoint L3 P9
  midpoint A2 P10
  parallel L5 L7
  parallel L6 L8
  parallel L4 L7
  coincident A2 P15
  perpendicular L6 L9
  perpendicular L5 L8
  coincident A2 P16
  perpendicular L6 L10
  coincident A9 P52
  perpendicular L8 L24
  coincident L7 P54
  coincident L8 P53
  midpoint P14 A16
  dimension "d462" distance L4 L7 = 12
  dimension "d463" distance L4 L5 = 12 (= "d462")
  dimension "d464" distance P13 P14 = 5
  dimension "d466" distance P13 P15 = 1
  dimension "d469" radius A16 = 3.1
extrude "Extrude35" cut sketch "Sketch67" profile of A1 A2 L5 L6 L7 L8 L9 L10 A8 A9 A15 L24 A16 against normal blind 15.8 (magnitude of "-( 2.80 mm + 13 mm )")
